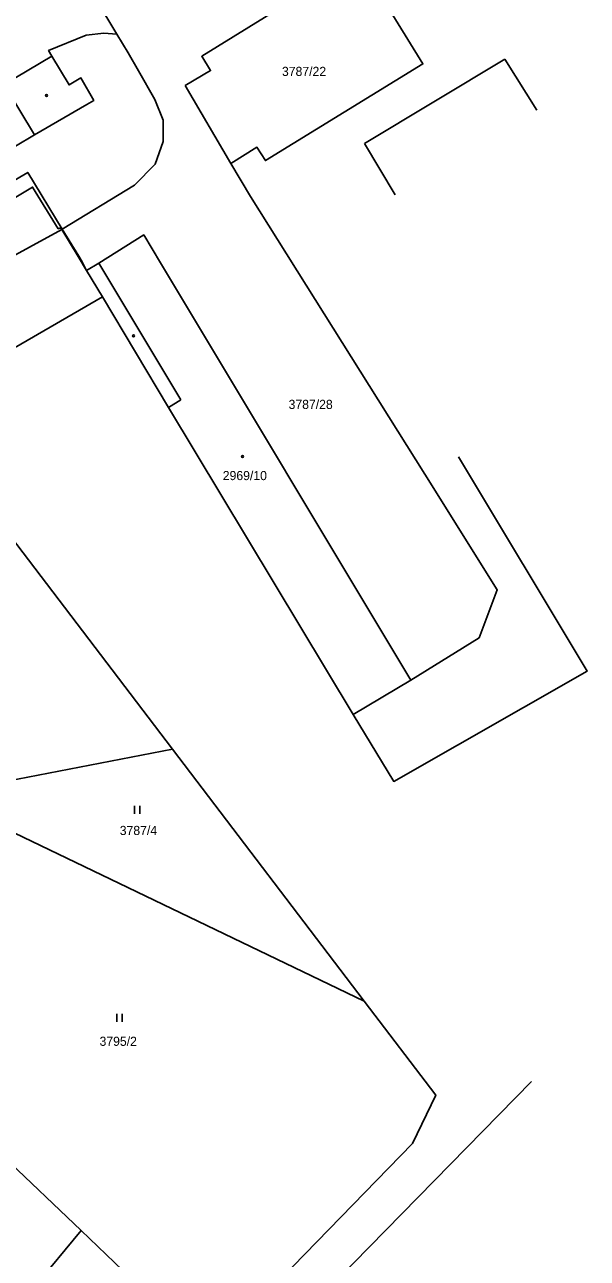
# Model space of a CAD drawing. Extents: x -527335 to -526256, y -1079142 to -1077836.
# Drawn here: x -526473.7 to -526369, y -1078894.6 to -1078664.8 of the extents above; entities that cross this region are included whole.
import ezdxf

# ---------------------------------------------------------------- set-up
doc = ezdxf.new("R2010")
doc.units = 0
for name, color, linetype in [('Hranice parcel', 7, 'Continuous'), ('Parcelní čísla', 7, 'Continuous'), ('Vnitřní kresba', 7, 'Continuous'), ('Značky budov', 7, 'Continuous'), ('Značky kultur', 7, 'Continuous')]:
    doc.layers.add(name, color=color, linetype=linetype)

msp = doc.modelspace()

# ---------------------------------------------------------------- linework, layer by layer
at = {"layer": 'Hranice parcel'}
for p, q in [((-526456.6, -1078666.52), (-526460.45, -1078660.06)), ((-526443.9, -1078676.11), (-526435.4, -1078690.65)), ((-526462.23, -1078710.59), (-526459.29, -1078715.49)), ((-526412.59, -1078793.3), (-526401.86, -1078786.86)), ((-526490.41, -1078808.25), (-526446.22, -1078799.76)), ((-526410.53, -1078846.68), (-526446.22, -1078799.76)), ((-526490.41, -1078808.25), (-526410.53, -1078846.68)), ((-526477.68, -1078875.63), (-526463.23, -1078889.43)), ((-526463.23, -1078889.43), (-526494.04, -1078926.52)), ((-526463.23, -1078889.43), (-526439.43, -1078912.18))]:
    msp.add_line(p, q, dxfattribs=at)
for points in [[(-526443.9, -1078676.11), (-526439.15, -1078673.33), (-526440.79, -1078670.66), (-526411.59, -1078652.55), (-526399.61, -1078672.09), (-526428.92, -1078690.08), (-526430.5, -1078687.59), (-526435.4, -1078690.65)], [(-526468.68, -1078670.61), (-526469.29, -1078669.59), (-526462.28, -1078666.74), (-526459.03, -1078666.34), (-526456.6, -1078666.52)], [(-526466.75, -1078702.85), (-526453.28, -1078694.69), (-526449.45, -1078690.73), (-526447.95, -1078686.51), (-526447.99, -1078682.56), (-526449.52, -1078678.69), (-526452.57, -1078673.36), (-526454.51, -1078670.02), (-526456.6, -1078666.52)], [(-526489.02, -1078681.76), (-526502.8, -1078689.9), (-526496.73, -1078700.04), (-526471.91, -1078685.32), (-526462.19, -1078679.64), (-526460.89, -1078678.88), (-526463.29, -1078674.7), (-526465.49, -1078675.98), (-526468.68, -1078670.61)], [(-526468.68, -1078670.61), (-526477.58, -1078675.89), (-526477.94, -1078675.21), (-526489.02, -1078681.76)], [(-526462.23, -1078710.59), (-526463.8, -1078707.96), (-526466.85, -1078702.91), (-526467.03, -1078702.61), (-526467.49, -1078702.78), (-526472.28, -1078695.01), (-526498.02, -1078710.48), (-526500.77, -1078711.52), (-526509.45, -1078708.26), (-526551.68, -1078690.31), (-526565.07, -1078683.93), (-526564.67, -1078683.01)], [(-526466.75, -1078702.85), (-526473.18, -1078692.3), (-526502.09, -1078709.21), (-526504.91, -1078709.68), (-526552.77, -1078689.34), (-526564.67, -1078683.01)], [(-526435.4, -1078690.65), (-526431.69, -1078696.75), (-526399.26, -1078748.53), (-526385.76, -1078770.08), (-526389.12, -1078778.99), (-526401.86, -1078786.86)], [(-526462.23, -1078710.59), (-526463.05, -1078708.92), (-526463.68, -1078707.89), (-526466.75, -1078702.85)], [(-526401.86, -1078786.86), (-526448.44, -1078709.15), (-526451.57, -1078703.93), (-526459.97, -1078709.18), (-526462.23, -1078710.59)], [(-526516.89, -1078712.01), (-526480.01, -1078727.48), (-526459.29, -1078715.49)], [(-526459.29, -1078715.49), (-526446.98, -1078736.06), (-526412.59, -1078793.3)], [(-526446.22, -1078799.76), (-526494.18, -1078736.71), (-526500.66, -1078729.66)], [(-526393.01, -1078745.25), (-526369.01, -1078785.21), (-526405.04, -1078805.76), (-526412.59, -1078793.3)], [(-526410.53, -1078846.68), (-526397.22, -1078864.18), (-526401.55, -1078873.2), (-526439.43, -1078912.18)], [(-526464.58, -1078955.73), (-526463.83, -1078947.95), (-526379.39, -1078861.67)]]:
    msp.add_lwpolyline(points, dxfattribs=at)
at = {"layer": 'Vnitřní kresba'}
for p, q in [((-526410.47, -1078686.93), (-526384.37, -1078671.18)), ((-526384.37, -1078671.18), (-526378.4, -1078680.72)), ((-526477.58, -1078675.89), (-526471.91, -1078685.32)), ((-526404.76, -1078696.48), (-526410.47, -1078686.93)), ((-526466.85, -1078702.91), (-526478.94, -1078709.54)), ((-526466.75, -1078702.85), (-526466.85, -1078702.91)), ((-526459.97, -1078709.18), (-526444.66, -1078734.67)), ((-526444.66, -1078734.67), (-526446.98, -1078736.06))]:
    msp.add_line(p, q, dxfattribs=at)
at = {"layer": 'Značky budov'}
for centre in [(-526469.67, -1078677.95), (-526453.48, -1078722.74), (-526433.19, -1078745.22)]:
    msp.add_circle(centre, 0.175, dxfattribs=at)
at = {"layer": 'Značky kultur'}
for p, q in [((-526453.29, -1078811.8), (-526453.29, -1078810.3)), ((-526452.29, -1078811.8), (-526452.29, -1078810.3)), ((-526456.6, -1078850.57), (-526456.6, -1078849.07)), ((-526455.6, -1078850.57), (-526455.6, -1078849.07))]:
    msp.add_line(p, q, dxfattribs=at)

# ---------------------------------------------------------------- texts
at = {"layer": 'Parcelní čísla'}
for s, p in [('3787/22', (-526425.85, -1078674.32)), ('3787/28', (-526424.62, -1078736.36)), ('2969/10', (-526436.87, -1078749.62)), ('3787/4', (-526456.05, -1078815.74)), ('3795/2', (-526459.81, -1078855.02))]:
    msp.add_text(s, height=1.7, dxfattribs=at).set_placement(p)

doc.saveas('drawing.dxf')
